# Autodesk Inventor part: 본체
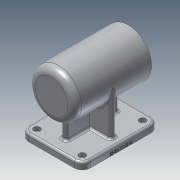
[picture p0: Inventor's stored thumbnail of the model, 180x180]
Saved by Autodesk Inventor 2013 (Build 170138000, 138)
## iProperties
Created: 2020-10
Part Number: 본체
Material: 알루미늄 6061
Document SubType Name: Modeling
Designer: 00
Density: 2.71 g/cm^3
Mass: 1029.93 g
Surface Area: 758.371 cm^2
Volume: 380.048 cm^3
Author: 00
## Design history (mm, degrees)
sketch "스케치1"
  geometry: L1 (0, 56)-(0, -56); L2 (0, 56)-(34, 56); L3 (34, 56)-(34, -56); L4 (34, -56)-(0, -56); 2 further points
  constraints: 8 end point, 2 perpendicular, 1 coincident, 1 midpoint, 1 parallel, 1 vertical
  dimensions: "d0" = 112 distance of L1.start L1.end; "d2" = 68 diameter of L3 L1
revolve "회전1" sketch "스케치1" stored, may be unused: angle "d3" = 90 deg
node "작업 평면1"
sketch "스케치2"
  geometry: L1 (-45, -56)-(45, -56); L2 (45, -56)-(45, 56); L3 (45, 56)-(-45, 56); L4 (-45, 56)-(-45, -56); L5 (-45, -56)-(45, 56); L6 (45, -56)-(-45, 56); 1 further point
  constraints: 12 end point, 2 midpoint, 2 parallel, 1 horizontal, 1 perpendicular
  dimensions: "d5" = 112 distance of L1.end L2.end; "d7" = 90 distance between parallel lines of L4 L2
extrude "돌출1" join sketch "스케치2" distance "d8" = 10; taper "d9" = 0 deg
sketch "스케치3"
  geometry: L1 (-34, -4)-(34, -4); L2 (34, -4)-(34, 4); L3 (34, 4)-(-34, 4); L4 (-34, 4)-(-34, -4); L5 (-34, -4)-(34, 4); L6 (34, -4)-(-34, 4); L7 (34, 56)-(-34, 56) reference; L8 (34, -56)-(-34, -56) reference; 1 further point
  constraints: 12 end point, 2 midpoint, 2 parallel, 1 horizontal, 1 perpendicular
  dimensions: "d10" = 8 distance of L1.end L2.end; "d12" = 68 distance between parallel lines of L4 L2
extrude "돌출2" join sketch "스케치3" stored distance "d13" = 10; taper "d14" = 0 deg
sketch "스케치4"
  geometry: L1 (34, 56)-(34, -56) reference; L2 (34, -56)-(-34, -56) reference; L3 (-34, -56)-(-34, -4) reference; L4 (-34, -4)-(-64, -4) reference; L5 (-64, -4)-(-64, -56) reference; L6 (-64, -56)-(-74, -56) reference; L7 (-74, -56)-(-74, 56) reference; L8 (-74, 56)-(-64, 56) reference; L9 (-64, 56)-(-64, 4) reference; L10 (-64, 4)-(-34, 4) reference; L11 (-34, 4)-(-34, 56) reference; L12 (-34, 56)-(34, 56) reference; L13 (-64, 38)-(-34, 38); 1 further point
  constraints: 2 end point, 2 point on line, 1 perpendicular
  dimensions: "d15" = 18 distance between parallel lines of L8 L13
feature "리브1" sketch "스케치4" dims "d16" = 1, "d17" = 8, "d18" = 0, "d19" = 0, "d20" = 1, "d21" = 1
sketch "스케치5"
  geometry: L1 (-64, 56)-(-64, 38) reference; L2 (-64, 38)-(-34, 38) reference; L3 (-34, 38)-(-34, 56) reference; L4 (-34, 56)-(34, 56) reference; L5 (34, 56)-(34, -56) reference; L6 (34, -56)-(-34, -56) reference; L7 (-34, -56)-(-34, -38) reference; L8 (-34, -38)-(-64, -38) reference; L9 (-64, -38)-(-64, -56) reference; L10 (-64, -56)-(-74, -56) reference; L11 (-74, -56)-(-74, 56) reference; L12 (-74, 56)-(-64, 56) reference; L13 (0, 56)-(0, -56); L14 (0, 50)-(10.5, 50); L15 (10.5, 50)-(10.5, 47); L16 (10.5, 47)-(16, 47); L17 (16, 47)-(16, 43); L18 (16, 43)-(17.5, 43); L19 (17.5, 43)-(17.5, 25); L20 (17.5, 25)-(21, 25); L21 (21, 25)-(21, 13); L22 (21, 13)-(24, 13); L23 (24, 13)-(24, -41); L24 (24, -41)-(21, -41); L25 (21, -41)-(21, -56); L26 (21, -56)-(0, -56); 1 further point
  constraints: 28 end point, 7 perpendicular, 5 parallel, 2 midpoint, 2 point on line, 1 collinear
  dimensions: "d22" = 15 distance of L24.end L25.end; "d24" = 54 distance of L22.end L23.end; "d25" = 12 distance of L20.end L21.end; "d26" = 18 distance of L18.end L19.end; "d27" = 4 distance of L16.end L17.end; "d28" = 3 distance of L14.end L15.end; "d29" = 42 diameter of L25 L13; "d30" = 48 diameter of L23 L13; "d31" = 42 diameter of L21 L13; "d32" = 35 diameter of L19 L13; "d33" = 32 diameter of L17 L13; "d34" = 21 diameter of L15 L13
revolve "회전2" sketch "스케치5" stored, may be unused: angle "d35" = 90 deg
fillet "모깎기1" dims "d36" = 0.3
fillet "모깎기2" dims "d37" = 3
fillet "모깎기3" dims "d38" = 12
sketch "스케치6"
  geometry: A1 r 12 centre (-33, 44) between (-33, 56) and (-45, 44) reference; A2 r 12 centre (-33, -44) between (-45, -44) and (-33, -56) reference; A3 r 12 centre (33, -44) between (33, -56) and (45, -44) reference; A4 r 12 centre (33, 44) between (45, 44) and (33, 56) reference; 5 further points
  constraints: 4 coincident
hole "구멍1" sketch "스케치6" at (-33, 44), (33, 44), (33, -44), (-33, -44) diameter "d39" = 5.5; stored, may be unused: countersink angle "d43" = 90 deg, drill point angle "d45" = 0 deg; dims "d40" = 6, "d41" = 9.5, "d42" = 5.4, "d44" = 8
fillet "모깎기4" dims "d46" = 10
sketch "스케치7"
  geometry: L1 (0, 0)-(88, 0) reference; L2 (100, 0)-(100, 10) reference; 2 further points
  constraints: 1 other
  dimensions: "d47" = 56 distance from line of L2 point (44, 3); "d48" = 3 distance from line of L1 point (44, 3)
feature "엠보싱1" sketch "스케치7" dims "d0" = 112, "d2" = 68, "d49" = 0.5, "d50" = 0
sketch "스케치8"
  geometry: C1 r 21 at (0, 0) reference; C2 r 34 at (0, 0) reference; A1 r 26 centre (0, 0) between (0, 26) and (-26, 0); 2 further points
  constraints: 4 point on circle, 2 horizontal alignment, 2 vertical alignment, 1 centre point, 1 coincident
  dimensions: "d51" = 52 diameter of A1
hole "구멍2" sketch "스케치8" at (0, 26), (-26, 0), (0, -26), (26, 0) diameter "d52" = 3.242; stored, may be unused: countersink angle "d56" = 90 deg, drill point angle "d58" = 118 deg; dims "d53" = 8, "d54" = 9.5, "d55" = 5.4, "d57" = 11
chamfer "모따기1" distance "d59" = 1; stored, may be unused: second distance "d60" = 2, angle "d61" = 45 deg
fillet "모깎기5" dims "d62" = 3
fillet "모깎기6" dims "d63" = 3
fillet "모깎기7" dims "d64" = 3
fillet "모깎기8" dims "d65" = 3
fillet "모깎기9" dims "d66" = 3
fillet "모깎기10" dims "d67" = 3
node "솔리드1"
mirror "대칭1"
node "투영된 루프1"
node "절단 모서리 투영1"
node "절단 모서리 투영2"
other parameters: "d4" = -74
